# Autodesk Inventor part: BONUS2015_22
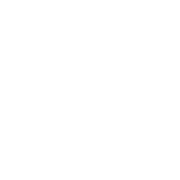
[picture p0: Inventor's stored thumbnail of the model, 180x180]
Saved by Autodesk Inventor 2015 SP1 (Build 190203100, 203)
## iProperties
Created: 2015-05
Part Number: BONUS2015_22
Material: Generisch
Document SubType Name: Modeling
Density: 1 g/cm^3
Appearance: Vorgabe
xx: 22
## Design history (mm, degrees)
